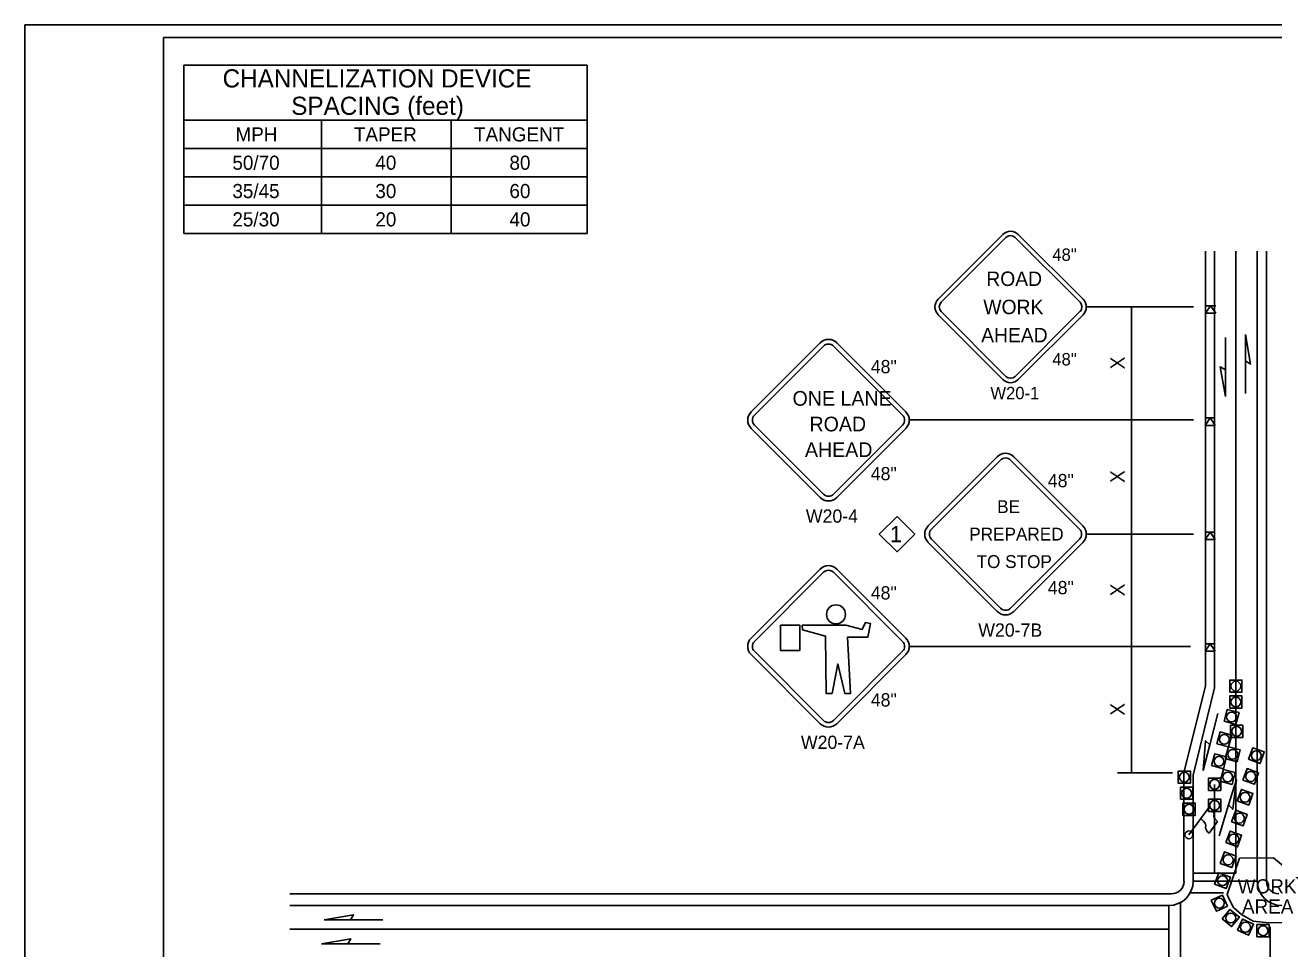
# Model space of a CAD drawing. Extents: x 99988 to 100172, y 99995 to 100047.
# Drawn here: x 99999.31 to 100005.5, y 100005.86 to 100010.44 of the extents above; entities that cross this region are included whole.
import ezdxf

# ---------------------------------------------------------------- set-up
doc = ezdxf.new("R2010")
doc.units = 0
for name, color, linetype in [('Default', 7, 'Continuous'), ('Level 15', 7, 'Continuous'), ('Level 20', 7, 'Continuous'), ('SH_DE_DetailBody1Text', 7, 'Continuous'), ('SH_GI_PlotLimits', 7, 'Continuous'), ('SH_GI_SheetBorder', 7, 'Continuous'), ('SH_GI_TrafficMvmntArrowRt1Lane', 7, 'Continuous'), ('SH_TI_ChanSpacing25to70Note', 7, 'Continuous'), ('SH_TI_SignSpacing35to70Note', 7, 'Continuous'), ('TR_SN_WarningSigns', 7, 'Continuous'), ('TR_WZ_FlaggingStation', 7, 'Continuous'), ('TR_WZ_TrafficSafetyCone', 7, 'Continuous'), ('TR_WZ_WorkZoneDetails', 7, 'Continuous')]:
    doc.layers.add(name, color=color, linetype=linetype)

msp = doc.modelspace()

# ---------------------------------------------------------------- linework, layer by layer
at = {"layer": 'Default'}
for p, q in [((100005.1657, 100009.0085), (100005.1912, 100009.0451)), ((100005.1657, 100009.0451), (100005.2167, 100009.0451)), ((100005.1657, 100009.0085), (100005.2167, 100009.0085)), ((100005.2167, 100009.0085), (100005.1912, 100009.0451)), ((100005.1636, 100008.4531), (100005.189, 100008.4896)), ((100005.1636, 100008.4896), (100005.2145, 100008.4896)), ((100005.1636, 100008.4531), (100005.2145, 100008.4531)), ((100005.2145, 100008.4531), (100005.189, 100008.4896)), ((100005.1636, 100007.8868), (100005.189, 100007.9234)), ((100005.1636, 100007.9234), (100005.2145, 100007.9234)), ((100005.2145, 100007.8868), (100005.189, 100007.9234)), ((100005.1636, 100007.8868), (100005.2145, 100007.8868)), ((100005.1636, 100007.3335), (100005.189, 100007.3701)), ((100005.1636, 100007.3701), (100005.2145, 100007.3701)), ((100005.2145, 100007.3335), (100005.189, 100007.3701)), ((100005.1636, 100007.3335), (100005.2145, 100007.3335))]:
    msp.add_line(p, q, dxfattribs=at)
msp.add_lwpolyline([(100005.3343, 100006.3083), (100005.5028, 100006.3097), (100005.714, 100006.133), (100005.714, 100006.003), (100005.6756, 100005.9908), (100005.4791, 100005.9876), (100005.4029, 100005.9966), (100005.3447, 100006.0286), (100005.3044, 100006.0632), (100005.2813, 100006.1074), (100005.2736, 100006.1272)], close=True, dxfattribs=at)
at = {"layer": 'Level 15'}
for p, q in [((100004.7995, 100009.0399), (100004.7995, 100008.7606)), ((100004.7995, 100008.4813), (100004.7995, 100008.7606)), ((100004.7995, 100008.4813), (100004.7995, 100008.1977)), ((100004.7995, 100007.9141), (100004.7995, 100008.1977)), ((100004.7995, 100007.9141), (100004.7995, 100007.6359)), ((100004.7995, 100007.3577), (100004.7995, 100007.6359)), ((100004.7995, 100007.3577), (100004.7995, 100007.0444)), ((100004.7995, 100006.731), (100004.7995, 100007.0444))]:
    msp.add_line(p, q, dxfattribs=at)
at = {"layer": 'SH_DE_DetailBody1Text'}
msp.add_lwpolyline([(100003.6362, 100008.0019), (100003.7239, 100007.9141), (100003.6362, 100007.8264), (100003.5484, 100007.9141)], close=True, dxfattribs=at)
at = {"layer": 'SH_GI_PlotLimits'}
msp.add_lwpolyline([(99999.3125, 99999.9375), (100015.8125, 99999.9375), (100015.8125, 100010.4375), (99999.3125, 100010.4375)], close=True, dxfattribs=at)
at = {"layer": 'SH_GI_SheetBorder'}
for q in [(100000, 100000), (100015.75, 100010.375)]:
    msp.add_line((100000, 100010.375), q, dxfattribs=at)
at = {"layer": 'SH_GI_TrafficMvmntArrowRt1Lane'}
for p, q in [((100005.2642, 100008.7276), (100005.2642, 100008.8883)), ((100005.3633, 100008.7721), (100005.3633, 100008.6114)), ((100005.1867, 100006.8693), (100005.2267, 100007.025)), ((100005.2806, 100006.5727), (100005.2328, 100006.4193)), ((100000.9265, 100006.0022), (100001.0873, 100006.0022)), ((100000.9133, 100005.8832), (100001.0741, 100005.8832))]:
    msp.add_line(p, q, dxfattribs=at)
for points in [[(100005.3633, 100008.9031), (100005.389, 100008.7572), (100005.3633, 100008.7721)], [(100005.2642, 100008.5966), (100005.2384, 100008.7425), (100005.2642, 100008.7276)], [(100005.154, 100006.7424), (100005.1655, 100006.8901), (100005.1867, 100006.8693)], [(100005.3195, 100006.6978), (100005.3007, 100006.5509), (100005.2806, 100006.5727)], [(100000.7955, 100006.0022), (100000.9414, 100006.0279), (100000.9265, 100006.0022)], [(100000.7823, 100005.8832), (100000.9282, 100005.9089), (100000.9133, 100005.8832)]]:
    msp.add_lwpolyline(points, close=True, dxfattribs=at)
at = {"layer": 'SH_TI_ChanSpacing25to70Note'}
for p, q in [((100000.1004, 100009.9654), (100002.1004, 100009.9654)), ((100000.7831, 100009.4039), (100000.7831, 100009.9654)), ((100001.4252, 100009.4039), (100001.4252, 100009.9654)), ((100000.1004, 100009.825), (100002.1004, 100009.825)), ((100000.1004, 100009.6847), (100002.1004, 100009.6847)), ((100000.1004, 100009.5443), (100002.1004, 100009.5443))]:
    msp.add_line(p, q, dxfattribs=at)
at = {"layer": 'SH_TI_SignSpacing35to70Note'}
for p, q in [((100000.1004, 100010.2383), (100000.1004, 100009.4039)), ((100000.1004, 100010.2383), (100002.1004, 100010.2383)), ((100002.1004, 100010.2383), (100002.1004, 100009.4039)), ((100000.1004, 100009.4039), (100002.1004, 100009.4039))]:
    msp.add_line(p, q, dxfattribs=at)
at = {"layer": 'TR_SN_WarningSigns'}
for p, q in [((100003.8398, 100009.0782), (100004.1611, 100009.3994)), ((100003.8551, 100009.0629), (100004.1764, 100009.3841)), ((100004.2223, 100009.3841), (100004.5436, 100009.0629)), ((100004.2376, 100009.3994), (100004.5588, 100009.0782)), ((100004.1764, 100008.6957), (100003.8551, 100009.017)), ((100004.5435, 100009.017), (100004.2223, 100008.6957)), ((100004.1611, 100008.6804), (100003.8398, 100009.0017)), ((100004.5588, 100009.0017), (100004.2376, 100008.6804)), ((100002.9131, 100008.5198), (100003.2558, 100008.8625)), ((100002.9294, 100008.5035), (100003.2721, 100008.8462)), ((100003.321, 100008.8462), (100003.6637, 100008.5035)), ((100003.3374, 100008.8625), (100003.68, 100008.5198)), ((100003.2721, 100008.1119), (100002.9294, 100008.4545)), ((100003.6637, 100008.4545), (100003.321, 100008.1119)), ((100003.2558, 100008.0955), (100002.9131, 100008.4382)), ((100003.68, 100008.4382), (100003.3374, 100008.0955)), ((100003.7908, 100007.9549), (100004.1335, 100008.2976)), ((100003.8072, 100007.9386), (100004.1498, 100008.2813)), ((100004.1988, 100008.2813), (100004.5415, 100007.9386)), ((100004.2151, 100008.2976), (100004.5578, 100007.9549)), ((100004.1335, 100007.5307), (100003.7908, 100007.8733)), ((100004.1498, 100007.547), (100003.8072, 100007.8897)), ((100004.5415, 100007.8897), (100004.1988, 100007.547)), ((100004.5578, 100007.8733), (100004.2151, 100007.5307)), ((100002.9131, 100007.3985), (100003.2557, 100007.7412)), ((100002.9294, 100007.3822), (100003.272, 100007.7249)), ((100003.321, 100007.7249), (100003.6637, 100007.3822)), ((100003.3373, 100007.7412), (100003.68, 100007.3985)), ((100003.2557, 100006.9743), (100002.9131, 100007.3169)), ((100003.272, 100006.9906), (100002.9294, 100007.3332)), ((100003.6637, 100007.3332), (100003.321, 100006.9906)), ((100003.68, 100007.3169), (100003.3373, 100006.9743))]:
    msp.add_line(p, q, dxfattribs=at)
for points in [[(100003.0579, 100007.4627), (100003.0579, 100007.338), (100003.1552, 100007.338), (100003.1552, 100007.4627)], [(100003.1666, 100007.463), (100003.168, 100007.4389), (100003.282, 100007.409), (100003.2845, 100007.1246), (100003.3141, 100007.1246), (100003.3423, 100007.2711), (100003.3778, 100007.1243), (100003.4064, 100007.1243), (100003.3902, 100007.4032), (100003.4912, 100007.4032), (100003.505, 100007.471), (100003.4793, 100007.4759), (100003.4629, 100007.4412), (100003.3825, 100007.463)]]:
    msp.add_lwpolyline(points, close=True, dxfattribs=at)
msp.add_circle((100003.3336, 100007.5164), 0.0471, dxfattribs=at)
for centre, radius, start, end in [((100004.1993, 100009.3612), 0.0541, 44.99628, 134.99965), ((100004.1993, 100009.3612), 0.0325, 44.99628, 134.99965), ((100003.8781, 100009.0399), 0.0541, 134.99658, 224.99358), ((100004.5206, 100009.0399), 0.0541, 314.99936, 44.99485), ((100003.8781, 100009.0399), 0.0325, 134.99658, 224.99358), ((100004.5206, 100009.0399), 0.0325, 314.99936, 44.99485), ((100003.2966, 100008.8217), 0.0577, 44.99628, 134.99965), ((100003.2966, 100008.8217), 0.0346, 44.99628, 134.99965), ((100004.1993, 100008.7187), 0.0541, 225, 314.99958), ((100004.1993, 100008.7187), 0.0325, 225, 314.99958), ((100002.9539, 100008.479), 0.0577, 134.99658, 224.99358), ((100003.6392, 100008.479), 0.0577, 314.99936, 44.99485), ((100002.9539, 100008.479), 0.0346, 134.99658, 224.99358), ((100003.6392, 100008.479), 0.0346, 314.99936, 44.99485), ((100004.1743, 100008.2568), 0.0577, 44.99628, 134.99965), ((100004.1743, 100008.2568), 0.0346, 44.99628, 134.99965), ((100003.2966, 100008.1363), 0.0577, 225, 314.99958), ((100003.2966, 100008.1363), 0.0346, 225, 314.99958), ((100003.8316, 100007.9141), 0.0577, 134.99658, 224.99358), ((100003.8316, 100007.9141), 0.0346, 134.99658, 224.99358), ((100004.517, 100007.9141), 0.0346, 314.99936, 44.99485), ((100004.517, 100007.9141), 0.0577, 314.99936, 44.99485), ((100003.2965, 100007.7004), 0.0577, 44.99628, 134.99965), ((100003.2965, 100007.7004), 0.0346, 44.99628, 134.99965), ((100004.1743, 100007.5715), 0.0577, 225, 314.99958), ((100004.1743, 100007.5715), 0.0346, 225, 314.99958), ((100002.9538, 100007.3577), 0.0577, 134.99658, 224.99358), ((100002.9538, 100007.3577), 0.0346, 134.99658, 224.99358), ((100003.6392, 100007.3577), 0.0346, 314.99936, 44.99485), ((100003.6392, 100007.3577), 0.0577, 314.99936, 44.99485), ((100003.2965, 100007.0151), 0.0577, 225, 314.99958), ((100003.2965, 100007.0151), 0.0346, 225, 314.99958)]:
    msp.add_arc(centre, radius, start, end, dxfattribs=at)
at = {"layer": 'TR_WZ_FlaggingStation'}
for p, q in [((100005.0833, 100006.4237), (100005.1842, 100006.5601)), ((100005.1433, 100006.5047), (100005.1843, 100006.5602)), ((100005.1433, 100006.5047), (100005.1433, 100006.5047)), ((100005.2253, 100006.4896), (100005.1832, 100006.4327))]:
    msp.add_line(p, q, dxfattribs=at)
for points in [[(100005.1843, 100006.5602), (100005.1869, 100006.5579), (100005.1952, 100006.5507), (100005.2011, 100006.5444), (100005.2043, 100006.5383), (100005.2073, 100006.5333), (100005.2082, 100006.5281), (100005.2081, 100006.5227), (100005.2065, 100006.5194), (100005.2065, 100006.513), (100005.2099, 100006.5058), (100005.2148, 100006.4994), (100005.2253, 100006.4896)], [(100005.1832, 100006.4327), (100005.1794, 100006.4359), (100005.1716, 100006.4436), (100005.1666, 100006.4538), (100005.1664, 100006.4612), (100005.1675, 100006.4677), (100005.166, 100006.4761), (100005.1622, 100006.4827), (100005.1553, 100006.4915), (100005.1433, 100006.5047)]]:
    msp.add_lwpolyline(points, dxfattribs=at)
msp.add_circle((100005.0833, 100006.4237), 0.0195, dxfattribs=at)
at = {"layer": 'TR_WZ_TrafficSafetyCone'}
for points in [[(100005.2858, 100007.1302), (100005.3465, 100007.1302), (100005.3465, 100007.1909), (100005.2858, 100007.1909)], [(100005.2858, 100007.0516), (100005.3465, 100007.0516), (100005.3465, 100007.1123), (100005.2858, 100007.1123)], [(100005.2576, 100006.9865), (100005.3163, 100006.9708), (100005.332, 100007.0294), (100005.2733, 100007.0451)], [(100005.2898, 100006.9065), (100005.3505, 100006.9065), (100005.3505, 100006.9672), (100005.2898, 100006.9672)], [(100005.222, 100006.8753), (100005.2806, 100006.8595), (100005.2963, 100006.9182), (100005.2377, 100006.9339)], [(100005.2639, 100006.8014), (100005.3226, 100006.7857), (100005.3383, 100006.8444), (100005.2796, 100006.8601)], [(100005.3793, 100006.7981), (100005.4364, 100006.7774), (100005.4571, 100006.8344), (100005.4001, 100006.8552)], [(100005.1958, 100006.7669), (100005.2544, 100006.7512), (100005.2702, 100006.8098), (100005.2115, 100006.8256)], [(100005.0303, 100006.6792), (100005.091, 100006.6792), (100005.091, 100006.7399), (100005.0303, 100006.7399)], [(100005.2385, 100006.6893), (100005.2972, 100006.6735), (100005.3129, 100006.7322), (100005.2542, 100006.7479)], [(100005.3513, 100006.6948), (100005.4083, 100006.6741), (100005.4291, 100006.7311), (100005.372, 100006.7519)], [(100005.0421, 100006.5997), (100005.1029, 100006.5997), (100005.1029, 100006.6604), (100005.0421, 100006.6604)], [(100005.1802, 100006.6437), (100005.241, 100006.6437), (100005.241, 100006.7044), (100005.1802, 100006.7044)], [(100005.1803, 100006.5392), (100005.2411, 100006.5392), (100005.2411, 100006.5999), (100005.1803, 100006.5999)], [(100005.3232, 100006.5916), (100005.3803, 100006.5708), (100005.4011, 100006.6279), (100005.344, 100006.6486)], [(100005.0539, 100006.5202), (100005.1147, 100006.5202), (100005.1147, 100006.5809), (100005.0539, 100006.5809)], [(100005.2952, 100006.4883), (100005.3523, 100006.4675), (100005.373, 100006.5246), (100005.316, 100006.5454)], [(100005.2672, 100006.385), (100005.3242, 100006.3642), (100005.345, 100006.4213), (100005.2879, 100006.4421)], [(100005.2391, 100006.2817), (100005.2962, 100006.261), (100005.317, 100006.318), (100005.2599, 100006.3388)], [(100005.2111, 100006.1784), (100005.2682, 100006.1577), (100005.2889, 100006.2147), (100005.2319, 100006.2355)], [(100005.1942, 100006.0999), (100005.2197, 100006.0448), (100005.2748, 100006.0703), (100005.2493, 100006.1254)], [(100005.2484, 100006.0073), (100005.2954, 100005.9688), (100005.3339, 100006.0158), (100005.2869, 100006.0543)], [(100005.3237, 100005.9508), (100005.3791, 100005.9258), (100005.404, 100005.9812), (100005.3486, 100006.0061)], [(100005.4209, 100005.9178), (100005.4816, 100005.9178), (100005.4816, 100005.9786), (100005.4209, 100005.9786)]]:
    msp.add_lwpolyline(points, close=True, dxfattribs=at)
for centre in [(100005.3161, 100007.1605), (100005.3161, 100007.0819), (100005.2948, 100007.008), (100005.2592, 100006.8967), (100005.3202, 100006.9368), (100005.3011, 100006.8229), (100005.233, 100006.7884), (100005.4182, 100006.8163), (100005.0607, 100006.7095), (100005.2757, 100006.7107), (100005.3902, 100006.713), (100005.2106, 100006.674), (100005.0725, 100006.63), (100005.3621, 100006.6097), (100005.0843, 100006.5505), (100005.2107, 100006.5695), (100005.3341, 100006.5064), (100005.3061, 100006.4032), (100005.278, 100006.2999), (100005.25, 100006.1966), (100005.2345, 100006.0851), (100005.2912, 100006.0115), (100005.3639, 100005.966), (100005.4513, 100005.9482)]:
    msp.add_circle(centre, 0.0244, dxfattribs=at)
at = {"layer": 'TR_WZ_WorkZoneDetails'}
for p, q in [((100005.1655, 100007.1629), (100005.1655, 100009.3162)), ((100005.211, 100007.1517), (100005.211, 100009.3162)), ((100005.3166, 100006.2333), (100005.3166, 100009.3162)), ((100005.4226, 100006.1943), (100005.4226, 100009.3162)), ((100005.4681, 100009.3162), (100005.4681, 100006.1924)), ((100005.1065, 100009.0399), (100004.5747, 100009.0399)), ((100005.1065, 100008.4813), (100003.6969, 100008.4813)), ((100005.1065, 100007.9141), (100004.5747, 100007.9141)), ((100005.0912, 100007.3577), (100003.6969, 100007.3577)), ((100005.1655, 100007.1629), (100005.0591, 100006.731)), ((100005.211, 100007.1517), (100005.1046, 100006.7198)), ((100005.0028, 100006.731), (100004.7295, 100006.731)), ((100005.0591, 100006.1924), (100005.0591, 100006.731)), ((100005.1046, 100006.1943), (100005.1046, 100006.7198)), ((100005.2106, 100006.2333), (100005.2106, 100006.674)), ((100005.1046, 100006.2333), (100005.3166, 100006.2333)), ((100005.1046, 100006.1943), (100005.4226, 100006.1943)), ((100000.6255, 100006.1318), (100004.9975, 100006.1318)), ((100005.0895, 100006.1357), (100005.2545, 100006.1357)), ((100000.6255, 100006.0731), (100004.9834, 100006.0731)), ((100004.9834, 100005.4863), (100004.9834, 100006.0731)), ((100005.042, 100005.4712), (100005.042, 100006.0882)), ((100000.6255, 100005.9557), (100004.9834, 100005.9557)), ((100005.487, 100005.3546), (100005.487, 100005.9676))]:
    msp.add_line(p, q, dxfattribs=at)
for centre, radius, start, end in [((100004.9834, 100006.1943), 0.1212, 270, 360), ((100004.9986, 100006.1924), 0.0606, 268.96062, 360), ((100005.5438, 100006.1943), 0.1212, 180, 270), ((100005.5287, 100006.1924), 0.0606, 180, 270)]:
    msp.add_arc(centre, radius, start, end, dxfattribs=at)

# ---------------------------------------------------------------- texts
at = {"layer": 'Level 20'}
for p in [(100004.7645, 100008.7309), (100004.7645, 100008.168), (100004.7645, 100007.6062), (100004.7645, 100007.0146)]:
    msp.add_text('X', height=0.07, rotation=90, dxfattribs=at).set_placement(p)
at = {"layer": 'SH_DE_DetailBody1Text'}
msp.add_text('1', height=0.08, dxfattribs=at).set_placement((100003.6011, 100007.8742))
for s, p in [('WORK', (100005.3258, 100006.1335)), ('AREA', (100005.3465, 100006.0335))]:
    msp.add_text(s, height=0.07, rotation=360, dxfattribs=at).set_placement(p)
at = {"layer": 'SH_TI_ChanSpacing25to70Note'}
for s, height, p in [('CHANNELIZATION DEVICE', 0.09, (100000.2925, 100010.1277)), ('SPACING (feet)', 0.09, (100000.6328, 100009.992)), ('MPH', 0.07, (100000.3562, 100009.8602)), ('TAPER', 0.07, (100000.9434, 100009.8602)), ('TANGENT', 0.07, (100001.5391, 100009.8602)), ('50/70', 0.07, (100000.3409, 100009.7199)), ('40', 0.07, (100001.0496, 100009.7199)), ('80', 0.07, (100001.7147, 100009.7199)), ('35/45', 0.07, (100000.3409, 100009.5795)), ('30', 0.07, (100001.0496, 100009.5795)), ('60', 0.07, (100001.7147, 100009.5795)), ('25/30', 0.07, (100000.3409, 100009.4391)), ('20', 0.07, (100001.0496, 100009.4391)), ('40', 0.07, (100001.7147, 100009.4391))]:
    msp.add_text(s, height=height, dxfattribs=at).set_placement(p)
at = {"layer": 'TR_SN_WarningSigns'}
for s, height, p in [('48"', 0.06152, (100004.4064, 100009.2683)), ('ROAD', 0.07155, (100004.0789, 100009.1439)), ('WORK', 0.07155, (100004.0642, 100009.0042)), ('AHEAD', 0.07155, (100004.0535, 100008.8645)), ('48"', 0.06563, (100003.5062, 100008.7114)), ('48"', 0.06152, (100004.4064, 100008.7501)), ('W20-1', 0.06152, (100004.0992, 100008.5824)), ('ONE LANE', 0.07268, (100003.1182, 100008.5506)), ('ROAD', 0.07268, (100003.2022, 100008.4234)), ('AHEAD', 0.07268, (100003.1796, 100008.2962)), ('48"', 0.06563, (100003.5062, 100008.181)), ('48"', 0.06563, (100004.384, 100008.1465)), ('BE', 0.0636, (100004.1327, 100008.0186)), ('W20-4', 0.06563, (100003.1844, 100007.9708)), ('PREPARED', 0.0636, (100003.9944, 100007.8823)), ('TO STOP', 0.0636, (100004.0306, 100007.7461)), ('48"', 0.06563, (100003.5062, 100007.5901)), ('48"', 0.06563, (100004.384, 100007.6162)), ('W20-7B', 0.06563, (100004.0391, 100007.4059)), ('48"', 0.06563, (100003.5062, 100007.0598)), ('W20-7A', 0.06563, (100003.1597, 100006.8496))]:
    msp.add_text(s, height=height, dxfattribs=at).set_placement(p)

doc.saveas('drawing.dxf')
